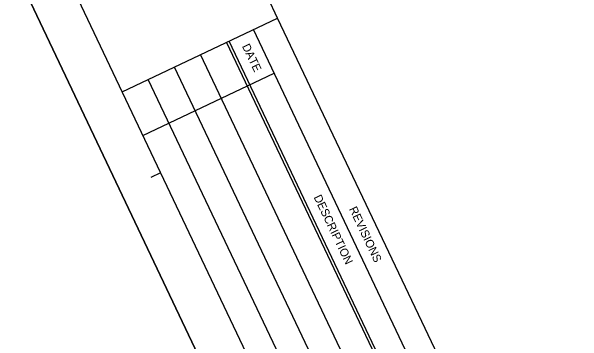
# Model space of a CAD drawing. Extents: x 1041072 to 1041761, y 1125784 to 1126587.
# Drawn here: x 1041192.1 to 1041324.8, y 1126056.1 to 1126132.8 of the extents above; entities that cross this region are included whole.
import ezdxf

# ---------------------------------------------------------------- set-up
doc = ezdxf.new("R2010")
doc.units = 0
for name, color, linetype in [('clip boundary', 7, 'Continuous'), ('SHEET_BORDER', 7, 'Continuous'), ('SHEET_BORDER_CUT', 7, 'Continuous'), ('SHEET_BORDER_STAMPBOX', 7, 'Continuous')]:
    doc.layers.add(name, color=color, linetype=linetype)

msp = doc.modelspace()

# ---------------------------------------------------------------- linework, layer by layer
at = {"layer": 'clip boundary'}
msp.add_lwpolyline([(1041469.06, 1126586.8), (1041760.77, 1125972.54), (1041363.32, 1125783.79), (1041071.61, 1126398.04)], close=True, dxfattribs=at)
at = {"layer": 'SHEET_BORDER'}
for p, q in [((1041217.85, 1126114.14), (1041253.98, 1126131.3)), ((1041217.85, 1126114.14), (1041253.98, 1126131.3)), ((1041398.04, 1125827.96), (1041253.98, 1126131.3)), ((1041299.77, 1126020.34), (1041248.34, 1126128.62)), ((1041299.77, 1126020.34), (1041248.34, 1126128.62)), ((1041293.55, 1126017.39), (1041242.13, 1126125.67)), ((1041294.13, 1126017.66), (1041242.71, 1126125.95)), ((1041294.13, 1126017.66), (1041242.71, 1126125.95)), ((1041287.48, 1126014.5), (1041236.06, 1126122.79)), ((1041281.41, 1126011.62), (1041229.99, 1126119.91)), ((1041275.34, 1126008.74), (1041223.92, 1126117.02)), ((1041226.78, 1126095.34), (1041224.52, 1126094.27))]:
    msp.add_line(p, q, dxfattribs=at)
msp.add_lwpolyline([(1041364.16, 1125811.87), (1041360.83, 1125813.06), (1041092.72, 1126377.63), (1041093.9, 1126380.96), (1041468.21, 1126558.72), (1041471.54, 1126557.53), (1041739.66, 1125992.96), (1041738.47, 1125989.63)], close=True, dxfattribs=at)
msp.add_lwpolyline([(1041222.67, 1126103.98), (1041253.17, 1126118.46)], dxfattribs=at)
at = {"layer": 'SHEET_BORDER_CUT'}
msp.add_lwpolyline([(1041071.61, 1126398.04), (1041363.32, 1125783.79), (1041760.77, 1125972.54), (1041469.06, 1126586.8)], close=True, dxfattribs=at)
at = {"layer": 'SHEET_BORDER_STAMPBOX'}
msp.add_line((1041253.98, 1126131.3), (1041195.61, 1126254.21), dxfattribs=at)

# ---------------------------------------------------------------- texts
at = {"layer": 'SHEET_BORDER'}
for s, p in [('DATE', (1041245.66, 1126124.76)), ('DESCRIPTION', (1041262.32, 1126089.67)), ('REVISIONS', (1041270.54, 1126086.93))]:
    msp.add_text(s, height=1.92, rotation=295.4032, dxfattribs=at).set_placement(p)

doc.saveas('drawing.dxf')
